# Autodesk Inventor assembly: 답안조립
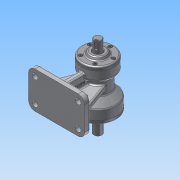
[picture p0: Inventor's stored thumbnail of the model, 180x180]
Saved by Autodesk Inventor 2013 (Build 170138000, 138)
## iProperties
Created: 2015-08
Part Number: 답안조립
Document SubType Name: Assembly
Designer: WINDOWS7
Author: WINDOWS7
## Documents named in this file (10)
- C:\Users\WINDOWS7\Desktop\450806V1030\답안조립.iam
- C:\Users\WINDOWS7\Desktop\450806V1030\본체.ipt
- C:\Users\WINDOWS7\Desktop\450806V1030\M4x0.5.ipt
- C:\Users\WINDOWS7\Desktop\450806V1030\뒤커버.ipt
- C:\Users\WINDOWS7\Desktop\450806V1030\베어링 6203.ipt
- C:\Users\WINDOWS7\Desktop\450806V1030\베어링 6205.ipt
- C:\Users\WINDOWS7\Desktop\450806V1030\앞커버.ipt
- C:\Users\WINDOWS7\Desktop\450806V1030\오일실 .ipt
- 오일실 .ipt
- C:\Users\WINDOWS7\Desktop\450806V1030\축.ipt
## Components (10 placed, 1 different names)
1. M4x0.5:1
2. M4x0.5:3
3. M4x0.5:4
4. M4x0.5:5
5. M4x0.5:6
6. M4x0.5:2
7. M4x0.5:7
8. M4x0.5:8
9. M4x0.5:9
10. M4x0.5:10
